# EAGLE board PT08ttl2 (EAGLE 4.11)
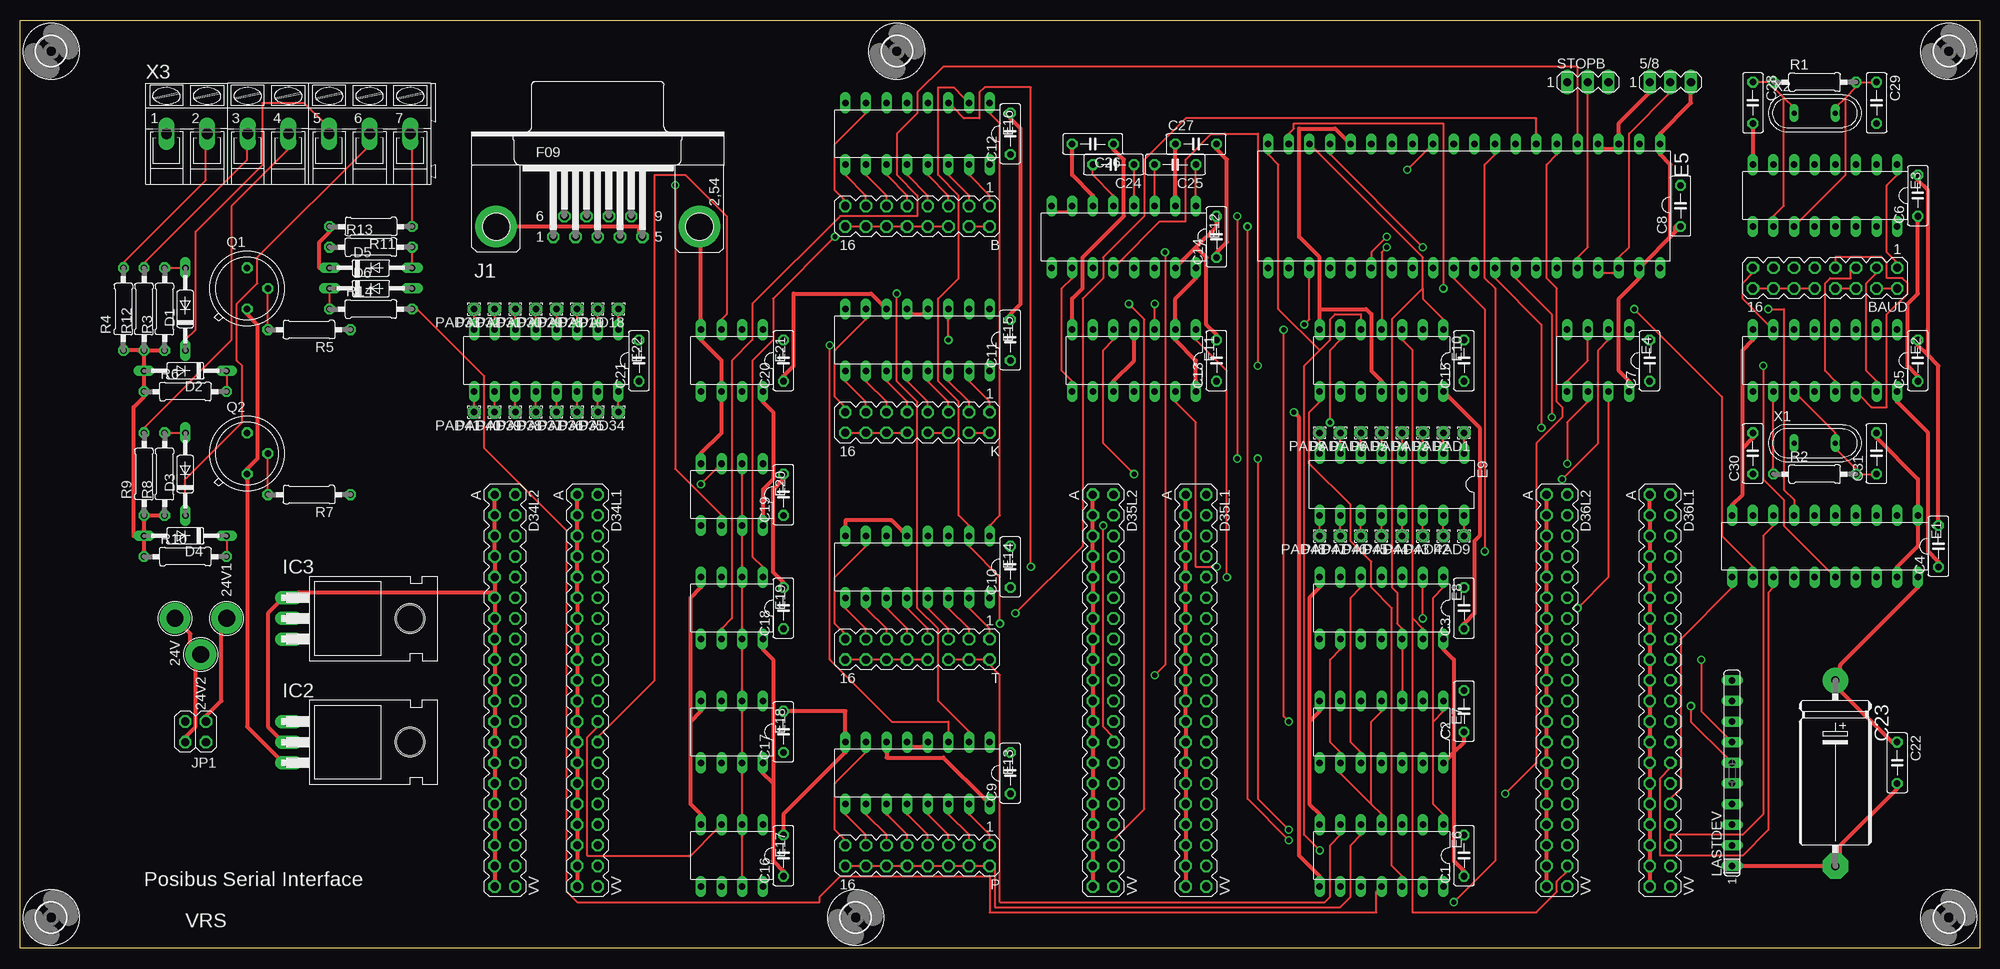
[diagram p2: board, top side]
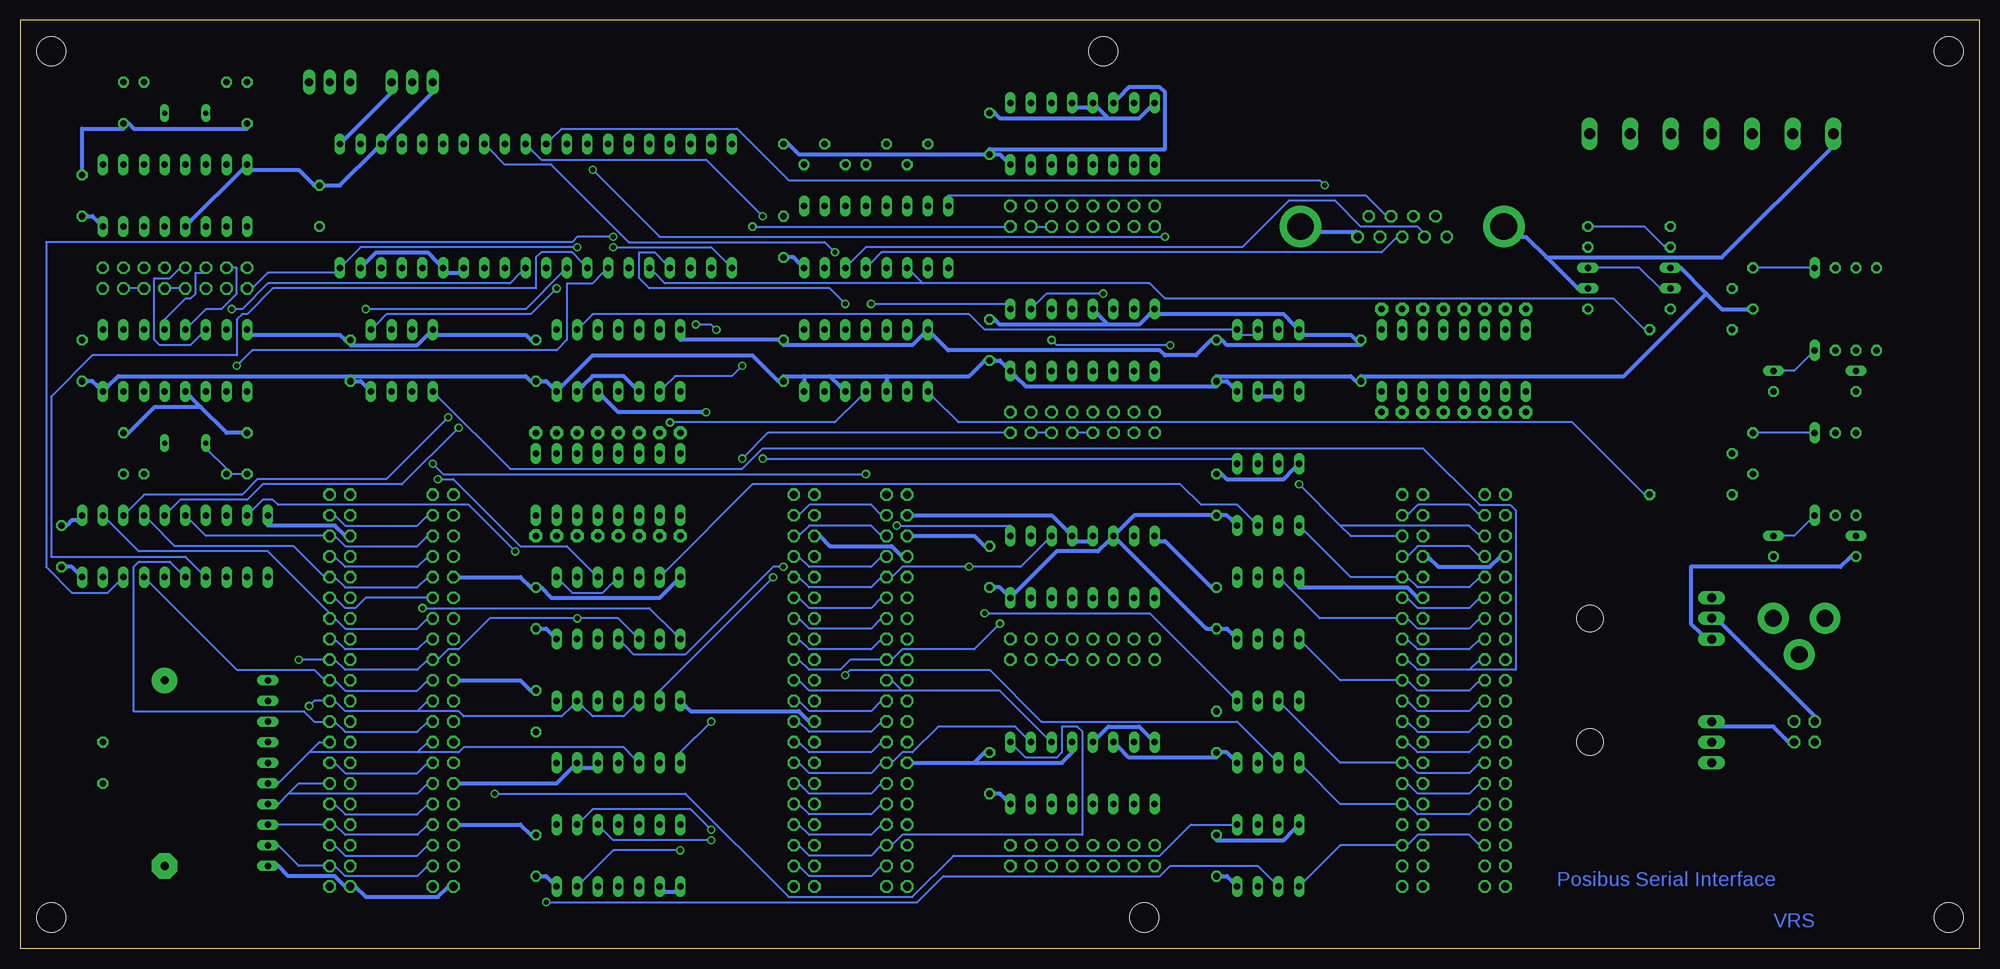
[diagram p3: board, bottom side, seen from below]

Size 241.3 x 114.3 mm. Coordinates in mm from the lower left corner, seen from the top.
Outline: 0,0 0,114.3 241.3,114.3 241.3,0 0,0
Copper layers (1*16): Top 0.035mm / dielectric 1.5mm / Bottom 0.035mm
Design rules "olimex10mil": minimum track width 10mil, minimum drill 24mil, track to track 10mil, track to pad 10mil, pad to pad 10mil, via to via 10mil, smd to smd 10mil, copper to edge 25mil, drill to drill 10mil, minimum pad ring 10mil, minimum via ring 8mil, stop-mask expansion 0mil, vias tented up to drill 0mil, thermal gap 10mil
Net classes: 1 supply: width 0.508 mm

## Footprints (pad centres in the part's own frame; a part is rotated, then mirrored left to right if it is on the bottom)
MA03-1 = drill 1.016 long: 1 -2.54,0; 2 0,0; 3 2.54,0
0820 = drill 2.083 pad 3.81 round: P$1 0,0
MA08-2 = drill 1.016 octagon: 1 -8.89,-1.27; 2 -8.89,1.27; 3 -6.35,-1.27; 4 -6.35,1.27; 5 -3.81,-1.27; 6 -3.81,1.27; 7 -1.27,-1.27; 8 -1.27,1.27; 9 1.27,-1.27; 10 1.27,1.27; 11 3.81,-1.27; 12 3.81,1.27; 13 6.35,-1.27; 14 6.35,1.27; 15 8.89,-1.27; 16 8.89,1.27
C050-025X075 = drill 0.813 octagon: 1 -2.54,0; 2 2.54,0
E22-9 = drill 1.016 pad 3.15 round: + -11.43,0 | drill 1.016 pad 3.15 octagon: - 11.43,0
DO35-10 = drill 0.813 long: A 5.08,0; C -5.08,0
DEC40PIN = drill 1.016 octagon: A -24.13,-1.27; AA 3.81,-1.27; B -24.13,1.27; BB 3.81,1.27; C -21.59,-1.27; CC 6.35,-1.27; D -21.59,1.27; DD 6.35,1.27; E -19.05,-1.27; EE 8.89,-1.27; F -19.05,1.27; FF 8.89,1.27; H -16.51,-1.27; HH 11.43,-1.27; J -16.51,1.27; JJ 11.43,1.27; K -13.97,-1.27; KK 13.97,-1.27; L -13.97,1.27; LL 13.97,1.27; M -11.43,-1.27; MM 16.51,-1.27; N -11.43,1.27; NN 16.51,1.27; P -8.89,-1.27; PP 19.05,-1.27; R -8.89,1.27; RR 19.05,1.27; S -6.35,-1.27; SS 21.59,-1.27; T -6.35,1.27; TT 21.59,1.27; U -3.81,-1.27; UU 24.13,-1.27; V -3.81,1.27; VV 24.13,1.27; W -1.27,-1.27; X -1.27,1.27; Y 1.27,-1.27; Z 1.27,1.27
DIL20 = drill 0.813 long: 1 -11.43,-3.81; 2 -8.89,-3.81; 3 -6.35,-3.81; 4 -3.81,-3.81; 5 -1.27,-3.81; 6 1.27,-3.81; 7 3.81,-3.81; 8 6.35,-3.81; 9 8.89,-3.81; 10 11.43,-3.81; 11 11.43,3.81; 12 8.89,3.81; 13 6.35,3.81; 14 3.81,3.81; 15 1.27,3.81; 16 -1.27,3.81; 17 -3.81,3.81; 18 -6.35,3.81; 19 -8.89,3.81; 20 -11.43,3.81
DIL16 = drill 0.813 long: 1 -8.89,-3.81; 2 -6.35,-3.81; 3 -3.81,-3.81; 4 -1.27,-3.81; 5 1.27,-3.81; 6 3.81,-3.81; 7 6.35,-3.81; 8 8.89,-3.81; 9 8.89,3.81; 10 6.35,3.81; 11 3.81,3.81; 12 1.27,3.81; 13 -1.27,3.81; 14 -3.81,3.81; 15 -6.35,3.81; 16 -8.89,3.81
DIL08 = drill 0.813 long: 1 -3.81,-3.81; 2 -1.27,-3.81; 3 1.27,-3.81; 4 3.81,-3.81; 5 3.81,3.81; 6 1.27,3.81; 7 -1.27,3.81; 8 -3.81,3.81
DIL40 = drill 0.813 long: 1 -24.13,-7.62; 2 -21.59,-7.62; 3 -19.05,-7.62; 4 -16.51,-7.62; 5 -13.97,-7.62; 6 -11.43,-7.62; 7 -8.89,-7.62; 8 -6.35,-7.62; 9 -3.81,-7.62; 10 -1.27,-7.62; 11 1.27,-7.62; 12 3.81,-7.62; 13 6.35,-7.62; 14 8.89,-7.62; 15 11.43,-7.62; 16 13.97,-7.62; 17 16.51,-7.62; 18 19.05,-7.62; 19 21.59,-7.62; 20 24.13,-7.62; 21 24.13,7.62; 22 21.59,7.62; 23 19.05,7.62; 24 16.51,7.62; 25 13.97,7.62; 26 11.43,7.62; 27 8.89,7.62; 28 6.35,7.62; 29 3.81,7.62; 30 1.27,7.62; 31 -1.27,7.62; 32 -3.81,7.62; 33 -6.35,7.62; 34 -8.89,7.62; 35 -11.43,7.62; 36 -13.97,7.62; 37 -16.51,7.62; 38 -19.05,7.62; 39 -21.59,7.62; 40 -24.13,7.62
DIL14 = drill 0.813 long: 1 -7.62,-3.81; 2 -5.08,-3.81; 3 -2.54,-3.81; 4 0,-3.81; 5 2.54,-3.81; 6 5.08,-3.81; 7 7.62,-3.81; 8 7.62,3.81; 9 5.08,3.81; 10 2.54,3.81; 11 0,3.81; 12 -2.54,3.81; 13 -5.08,3.81; 14 -7.62,3.81
TO220H = drill 1.118 long: 1 -2.54,-10.16; 2 0,-10.16; 3 2.54,-10.16 | hole 3.302: 0,4.826
F09HP = drill 1.016 octagon: 1 -5.486,-1.27; 2 -2.743,-1.27; 3 0,-1.27; 4 2.743,-1.27; 5 5.486,-1.27; 6 -4.115,1.27; 7 -1.372,1.27; 8 1.372,1.27; 9 4.115,1.27 | drill 3.302 pad 5.08 round: G1 -12.522,0; G2 12.522,0
2X02 = drill 1.016 octagon: 1 -1.27,-1.27; 2 -1.27,1.27; 3 1.27,-1.27; 4 1.27,1.27
SIL10 = drill 0.813 long: 1 -11.43,0; 2 -8.89,0; 3 -6.35,0; 4 -3.81,0; 5 -1.27,0; 6 1.27,0; 7 3.81,0; 8 6.35,0; 9 8.89,0; 10 11.43,0
1,6/0,8 = drill 0.813 pad 1.6 octagon: 1 0,0
TO39 = drill 0.813 octagon: 1 0,-2.54; 2 2.54,0; 3 0,2.54
0207/10 = drill 0.813 octagon: 1 -5.08,0; 2 5.08,0
3,6 = hole 3.6: 0,0
QS = drill 0.61 long: 1 -2.54,0; 2 2.54,0
AK300/7 = drill 1.321 long: 1 -15.011,0; 2 -10.008,0; 3 -5.004,0; 4 0,0; 5 5.004,0; 6 10.008,0; 7 15.011,0

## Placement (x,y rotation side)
5/8  [MA03-1]  203.2,106.68 0 top
24V  PAD-0820  [0820]  19.05,40.64 270 top
24V1  PAD-0820  [0820]  25.4,40.64 90 top
24V2  PAD-0820  [0820]  22.23,36.2 270 top
B  [MA08-2]  110.49,90.17 180 top
BAUD  [MA08-2]  222.25,82.55 180 top
C1  0.1  [C050-025X075]  177.8,11.43 90 top
C2  0.1  [C050-025X075]  177.8,29.21 90 top
C3  0.1  [C050-025X075]  177.8,41.91 90 top
C4  0.1  [C050-025X075]  236.22,49.53 90 top
C5  0.1  [C050-025X075]  233.68,72.39 90 top
C6  0.1  [C050-025X075]  233.68,92.71 90 top
C7  0.1  [C050-025X075]  200.66,72.39 90 top
C8  0.1  [C050-025X075]  204.47,91.44 90 top
C9  0.1  [C050-025X075]  121.92,21.59 90 top
C10  0.1  [C050-025X075]  121.92,46.99 90 top
C11  0.1  [C050-025X075]  121.92,74.93 90 top
C12  0.1  [C050-025X075]  121.92,100.33 90 top
C13  0.1  [C050-025X075]  147.32,72.39 90 top
C14  0.1  [C050-025X075]  147.32,87.63 90 top
C15  0.1  [C050-025X075]  177.8,72.39 90 top
C16  0.1  [C050-025X075]  93.98,11.43 90 top
C17  0.1  [C050-025X075]  93.98,26.67 90 top
C18  0.1  [C050-025X075]  93.98,41.91 90 top
C19  0.1  [C050-025X075]  93.98,55.88 90 top
C20  0.1  [C050-025X075]  93.98,72.39 90 top
C21  0.1  [C050-025X075]  76.2,72.39 90 top
C22  0.1  [C050-025X075]  231.14,22.86 270 top
C23  100uf  [E22-9]  223.52,21.59 270 top
C24  0.1  [C050-025X075]  134.62,96.52 180 top
C25  0.1  [C050-025X075]  142.24,96.52 180 top
C26  0.1  [C050-025X075]  132.08,99.06 180 top
C27  0.1  [C050-025X075]  144.78,99.06 0 top
C28  22pf  [C050-025X075]  213.36,104.14 270 top
C29  22pf  [C050-025X075]  228.6,104.14 270 top
C30  22pf  [C050-025X075]  213.36,60.96 90 top
C31  22pf  [C050-025X075]  228.6,60.96 90 top
D1  D664  [DO35-10]  20.32,78.74 90 top
D2  D664  [DO35-10]  20.32,71.12 180 top
D3  D664  [DO35-10]  20.32,58.42 90 top
D4  D664  [DO35-10]  20.32,50.8 180 top
D5  D664  [DO35-10]  43.18,83.82 0 top
D6  D664  [DO35-10]  43.18,81.28 0 top
D34L1  [DEC40PIN]  69.85,31.75 270 top
D34L2  [DEC40PIN]  59.69,31.75 270 top
D35L1  [DEC40PIN]  144.78,31.75 270 top
D35L2  [DEC40PIN]  133.35,31.75 270 top
D36L1  [DEC40PIN]  201.93,31.75 270 top
D36L2  [DEC40PIN]  189.23,31.75 270 top
E1  74HCT240N  [DIL20]  222.25,49.53 180 top
E2  74HCT4060N  [DIL16]  222.25,72.39 180 top
E3  74HCT4060N  [DIL16]  222.25,92.71 180 top
E4  DS75452N  [DIL08]  194.31,72.39 180 top
E5  HD6402  [DIL40]  177.8,91.44 180 top
E6  74LS02N  [DIL14]  167.64,11.43 180 top
E7  74HCT00N  [DIL14]  167.64,26.67 180 top
E8  74HCT08N  [DIL14]  167.64,41.91 180 top
E9  SPARE  [DIL16]  168.91,57.15 180 top
E10  74HCT04N  [DIL14]  167.64,72.39 180 top
E11  74HCT74N  [DIL14]  137.16,72.39 180 top
E12  MAX232  [DIL16]  135.89,87.63 180 top
E13  74LS138N  [DIL16]  110.49,21.59 180 top
E14  74LS138N  [DIL16]  110.49,46.99 180 top
E15  74LS138N  [DIL16]  110.49,74.93 180 top
E16  74LS138N  [DIL16]  110.49,100.33 180 top
E17  DS75452N  [DIL08]  87.63,11.43 180 top
E18  DS75452N  [DIL08]  87.63,26.67 180 top
E19  DS75452N  [DIL08]  87.63,41.91 180 top
E20  DS75452N  [DIL08]  87.63,55.88 180 top
E21  DS75452N  [DIL08]  87.63,72.39 180 top
E22  SPARE  [DIL16]  64.77,72.39 180 top
IC2  7805T  [TO220H]  43.18,25.4 270 top
IC3  7915T  [TO220H]  43.18,40.64 270 top
J1  [F09HP]  71.12,88.9 0 top
JP1  [2X02]  21.59,26.67 180 top
K  [MA08-2]  110.49,64.77 180 top
LASTDEV  100  [SIL10]  210.82,21.59 90 top
P  [MA08-2]  110.49,11.43 180 top
PAD1  [1,6/0,8]  177.8,63.5 180 top
PAD2  [1,6/0,8]  175.26,63.5 180 top
PAD3  [1,6/0,8]  172.72,63.5 180 top
PAD4  [1,6/0,8]  170.18,63.5 180 top
PAD5  [1,6/0,8]  167.64,63.5 180 top
PAD6  [1,6/0,8]  165.1,63.5 180 top
PAD7  [1,6/0,8]  162.56,63.5 180 top
PAD8  [1,6/0,8]  160.02,63.5 180 top
PAD9  [1,6/0,8]  177.8,50.8 180 top
PAD18  [1,6/0,8]  73.66,78.74 180 top
PAD19  [1,6/0,8]  71.12,78.74 180 top
PAD28  [1,6/0,8]  68.58,78.74 180 top
PAD29  [1,6/0,8]  66.04,78.74 180 top
PAD30  [1,6/0,8]  63.5,78.74 180 top
PAD31  [1,6/0,8]  60.96,78.74 180 top
PAD32  [1,6/0,8]  58.42,78.74 180 top
PAD33  [1,6/0,8]  55.88,78.74 180 top
PAD34  [1,6/0,8]  73.66,66.04 180 top
PAD35  [1,6/0,8]  71.12,66.04 180 top
PAD36  [1,6/0,8]  68.58,66.04 180 top
PAD37  [1,6/0,8]  66.04,66.04 180 top
PAD38  [1,6/0,8]  63.5,66.04 180 top
PAD39  [1,6/0,8]  60.96,66.04 180 top
PAD40  [1,6/0,8]  58.42,66.04 180 top
PAD41  [1,6/0,8]  55.88,66.04 180 top
PAD42  [1,6/0,8]  175.26,50.8 180 top
PAD43  [1,6/0,8]  172.72,50.8 180 top
PAD44  [1,6/0,8]  170.18,50.8 180 top
PAD45  [1,6/0,8]  167.64,50.8 180 top
PAD46  [1,6/0,8]  165.1,50.8 180 top
PAD47  [1,6/0,8]  162.56,50.8 180 top
PAD48  [1,6/0,8]  160.02,50.8 180 top
Q1  2N2904  [TO39]  27.94,81.28 0 top
Q2  2N2904  [TO39]  27.94,60.96 0 top
R1  10M  [0207/10]  220.98,106.68 0 top
R2  10M  [0207/10]  220.98,58.42 0 top
R3  1.5K 1/2W  [0207/10]  17.78,78.74 90 top
R4  750 1W  [0207/10]  12.7,78.74 90 top
R5  470  [0207/10]  35.56,76.2 180 top
R6  15K 1/2W  [0207/10]  20.32,68.58 0 top
R7  470  [0207/10]  35.56,55.88 180 top
R8  1.5K 1/2W  [0207/10]  17.78,58.42 90 top
R9  750 1W  [0207/10]  15.24,58.42 90 top
R10  15K 1/2W  [0207/10]  20.32,48.26 0 top
R11  750 1/2W  [0207/10]  43.18,88.9 180 top
R12  560 1/2W  [0207/10]  15.24,78.74 90 top
R13  82  [0207/10]  43.18,86.36 0 top
R14  3.3K  [0207/10]  43.18,78.74 0 top
STOPB  [MA03-1]  193.04,106.68 0 top
T  [MA08-2]  110.49,36.83 180 top
U$1  [3,6]  237.49,3.81 0 top
U$2  [3,6]  237.49,110.49 0 top
U$3  [3,6]  3.81,110.49 0 top
U$4  [3,6]  3.81,3.81 0 top
U$5  [3,6]  107.95,110.49 0 top
U$6  [3,6]  102.87,3.81 0 top
X1  2.4576Mhz  [QS]  220.98,62.23 0 top
X2  3.579545Mhz  [QS]  220.98,102.87 0 top
X3  [AK300/7]  33.02,100.33 0 top

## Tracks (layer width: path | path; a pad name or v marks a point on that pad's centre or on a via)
24V1
  Top 0.508: JP1.1 22.86,28.57 24.77,30.48 24.77,39.37 24V1.P$1
24V2
  Top 0.508: JP1.4 20.32,26.04 21.59,27.3 21.59,34.92 24V2.P$1 20.95,37.47 20.95,38.73 20.32,39.37 24V.P$1
+24V
  Bottom 0.508: JP1.2 23.5,25.4 25.4,27.3 31.75,27.3 IC2.1
-15V
  Top 0.508: R4.1 13.34,73.66 14.61,73.66 R12.1 | R3.1 17.14,73.66 15.88,73.66 R12.1 | R12.1 15.24,73.03 15.24,71.75 D2.A 15.24,70.48 15.24,69.22 R6.1 15.24,67.94 13.97,66.67 13.97,50.8 D4.A | R10.1 15.24,48.9 15.24,50.16 D4.A | D4.A 15.24,51.44 15.24,52.7 R9.1 15.88,53.34 17.14,53.34 R8.1
  Bottom 0.508: IC3.3 34.29,38.73 35.56,40.01 35.56,46.99 17.14,46.99 15.88,48.26 R10.1
-24V
  Bottom 0.508: JP1.3 20.32,28.57 31.75,40.01 IC3.2
ACB00\
  Bottom 0.254: D34L2.D 61.59,53.34 62.87,54.61 69.22,54.61 70.48,53.34 D34L1.D
ACB01\
  Bottom 0.254: D34L2.J 61.59,48.26 62.87,49.53 69.22,49.53 70.48,48.26 D34L1.J
ACB02\
  Bottom 0.254: D34L2.N 61.59,43.18 62.87,41.91 69.22,41.91 70.48,43.18 D34L1.N
ACB03\
  Bottom 0.254: D34L2.T 61.59,38.1 62.87,36.83 69.22,36.83 70.48,38.1 D34L1.T
ACB04\
  Bottom 0.254: E19.5 83.19,37.47 78.74,33.02 71.75,33.02 D34L1.X 70.48,33.02 69.22,31.75 62.87,31.75 61.59,33.02 D34L2.X
ACB05\
  Top 0.254: E17.3 85.72,14.61 82.55,11.43 69.85,11.43 69.85,26.04 71.12,27.3 D34L1.BB
  Bottom 0.254: D34L2.BB 61.59,27.94 62.87,26.67 69.22,26.67 70.48,27.94 D34L1.BB
ACB06\
  Bottom 0.254: E18.3 85.72,29.84 78.74,22.86 71.75,22.86 D34L1.FF 70.48,22.86 69.22,21.59 62.87,21.59 61.59,22.86 D34L2.FF
ACB07\
  Bottom 0.254: E18.5 83.19,22.23 78.74,17.78 71.75,17.78 D34L1.LL 70.48,17.78 69.22,16.51 62.87,16.51 61.59,17.78 D34L2.LL
ACB08\
  Bottom 0.254: E17.5 83.19,8.26 78.74,12.7 71.75,12.7 D34L1.RR 70.48,12.7 69.22,13.97 62.87,13.97 61.59,12.7 D34L2.RR
ACB09\  (via drill 0.61)
  Top 0.254: v83.82,57.15 85.72,59.05 E20.3
  Bottom 0.254: 78.74,52.07 77.47,50.8 71.75,50.8 D34L1.F | 78.74,52.07 v83.82,57.15 | 78.74,52.07 62.87,52.07 61.59,50.8 D34L2.F
ACB10\
  Bottom 0.254: E20.5 83.19,51.44 77.47,45.72 71.75,45.72 D34L1.L 70.48,45.72 69.22,44.45 62.87,44.45 61.59,45.72 D34L2.L
ACB11\
  Bottom 0.254: E19.3 85.72,45.09 81.28,40.64 71.75,40.64 D34L1.R 70.48,40.64 69.22,39.37 62.87,39.37 61.59,40.64 D34L2.R
ACCLEAR\
  Top 0.254: E21.3 86.36,77.47 87,78.11 87,90.17 81.92,95.25 78.11,95.25 78.11,33.02 71.12,26.04 D34L1.DD
  Bottom 0.254: D34L2.DD 61.59,25.4 62.87,24.13 69.22,24.13 70.48,25.4 D34L1.DD
B110
  Top 0.254: E3.1 231.14,95.25 229.87,93.98 229.87,85.72 231.14,84.45 BAUD.1
B150
  Top 0.254: E2.15 228.6,69.85 227.33,71.12 227.33,81.92 228.6,83.19 BAUD.3
B300
  Top 0.254: E2.13 223.52,69.85 222.25,71.12 222.25,81.92 222.88,82.55 225.43,82.55 225.43,83.82 BAUD.5
B600
  Top 0.254: E2.14 226.69,67.94 227.97,66.67 229.87,66.67 229.87,78.11 232.41,80.64 232.41,81.92 231.78,82.55 229.87,82.55 229.87,84.45 229.24,85.09 223.52,85.09 223.52,84.45 BAUD.7
B1200
  Bottom 0.254: E2.6 219.07,75.56 220.34,74.3 224.16,74.3 224.79,74.93 224.79,82.55 222.88,82.55 221.62,83.82 BAUD.9
B2400
  Bottom 0.254: E2.4 223.52,77.47 220.98,80.01 220.34,80.01 219.71,80.64 219.71,83.19 218.44,83.19 BAUD.11
B4800
  Bottom 0.254: E2.5 220.34,76.83 218.44,78.74 216.53,78.74 214.63,80.64 214.63,83.82 215.26,83.82 BAUD.13
B9600
  Top 0.254: E2.7 215.26,76.83 212.09,80.01 212.09,81.92 213.36,83.19 BAUD.15
B\  (via drill 0.61)
  Top 0.254: B.16 102.23,88.9 103.5,88.9 B.14 104.78,88.9 106.05,88.9 B.12 107.31,88.9 108.58,88.9 B.10 109.86,88.9 111.12,88.9 B.8 112.39,88.9 113.67,88.9 B.6 | v156.21,13.34 151.13,18.41 v151.13,88.9 | B.4 117.47,88.9 118.75,88.9 B.2
  Bottom 0.254: B.4 116.2,88.9 114.94,88.9 B.6 | v156.21,13.34 168.28,13.34 169.54,14.61 E6.3 | v151.13,88.9 120.02,88.9 B.2
BAC00
  Bottom 0.254: D36L2.D 191.13,53.34 192.41,52.07 201.29,52.07 202.56,53.34 D36L1.D
BAC01
  Bottom 0.254: D36L2.J 191.13,48.26 192.41,46.99 201.29,46.99 202.56,48.26 D36L1.J
BAC02
  Bottom 0.254: D36L2.N 191.13,43.18 198.75,43.18 200.03,41.91 201.29,41.91 202.56,43.18 D36L1.N
BAC03
  Bottom 0.254: D36L2.T 191.13,38.1 192.41,36.83 201.29,36.83 202.56,38.1 D36L1.T
BAC04
  Bottom 0.254: E1.17 225.43,45.09 214.63,34.29 205.1,34.29 203.84,33.02 D36L1.X 202.56,33.02 201.29,31.75 192.41,31.75 191.13,33.02 D36L2.X
BAC05
  Bottom 0.254: E1.15 221.62,46.35 222.88,47.62 226.69,47.62 227.33,46.99 227.33,29.21 206.38,29.21 205.1,27.94 203.84,27.94 D36L1.BB 202.56,27.94 201.29,26.67 192.41,26.67 191.13,27.94 D36L2.BB
BAC06
  Top 0.254: E1.13 215.9,44.45 215.26,43.81 215.26,14.61 212.09,11.43 201.93,11.43 201.93,20.95 203.2,22.23 D36L1.FF
  Bottom 0.254: D36L2.FF 191.13,22.86 192.41,21.59 201.29,21.59 202.56,22.86 D36L1.FF
BAC07
  Top 0.254: E1.11 210.82,44.45 204.47,38.1 204.47,19.68 203.2,18.41 D36L1.LL
  Bottom 0.254: D36L2.LL 191.13,17.78 192.41,16.51 201.29,16.51 202.56,17.78 D36L1.LL
BAC08
  Top 0.254: E1.8 215.9,52.07 214.63,50.8 214.63,16.51 212.09,13.97 203.2,13.97 203.2,13.34 D36L1.RR
  Bottom 0.254: D36L2.RR 191.13,12.7 192.41,11.43 201.29,11.43 202.56,12.7 D36L1.RR
BAC09
  Bottom 0.254: E1.6 220.34,52.7 218.44,50.8 203.84,50.8 D36L1.F 202.56,50.8 201.29,49.53 192.41,49.53 191.13,50.8 D36L2.F
BAC10
  Bottom 0.254: E1.4 225.43,52.7 222.25,49.53 207.65,49.53 203.84,45.72 D36L1.L 202.56,45.72 201.29,44.45 192.41,44.45 191.13,45.72 D36L2.L
BAC11
  Bottom 0.254: E1.2 230.5,52.7 226.69,48.9 210.82,48.9 203.2,41.27 D36L1.R 202.56,40.64 201.29,39.37 192.41,39.37 191.13,40.64 D36L2.R
BCLK  (via drill 0.61)
  Top 0.254: BAUD.16 214,81.28 215.26,81.28 BAUD.14 216.53,81.28 217.81,81.28 BAUD.12 219.07,81.28 220.34,81.28 BAUD.10 | BAUD.6 225.43,81.28 224.16,81.28 BAUD.8 | BAUD.2 230.5,81.28 229.24,81.28 BAUD.4 | v172.72,86.36 161.29,97.79 E5.17
  Bottom 0.254: BAUD.8 222.88,81.28 221.62,81.28 BAUD.10 | BAUD.4 227.97,81.28 226.69,81.28 BAUD.6 | v172.72,86.36 199.39,86.36 201.29,84.45 E5.40 202.56,83.19 210.82,83.19 212.72,81.28 BAUD.16
BINIT\
  Top 0.254: 171.45,40.64 172.72,39.37 E8.13 | 171.45,40.64 171.45,73.66 170.18,74.93 E10.3 | 171.45,40.64 171.45,4.45 186.69,4.45 189.23,6.99 189.23,8.26 190.5,9.53 D36L2.TT
  Bottom 0.254: LASTDEV.2 209.55,12.7 207.01,10.16 203.84,10.16 D36L1.TT 202.56,10.16 201.29,8.89 192.41,8.89 191.13,10.16 D36L2.TT
BIOP1  (via drill 0.61)
  Top 0.254: v207.01,35.56 207.01,29.21 210.19,26.04 LASTDEV.7 | v172.72,40.64 172.72,44.45 E8.2
  Bottom 0.254: v207.01,35.56 203.84,35.56 D36L1.V 202.56,35.56 201.29,34.29 192.41,34.29 191.13,35.56 D36L2.V 189.87,35.56 188.59,36.83 187.32,36.83 183.51,40.64 v172.72,40.64 167.64,40.64 165.74,38.73 E8.10
BIOP2  (via drill 0.61)
  Top 0.254: v205.74,29.84 205.74,27.94 210.19,23.5 LASTDEV.6
  Bottom 0.254: E7.5 165.74,29.84 167,28.57 170.81,28.57 172.09,29.84 E7.2 173.35,29.84 174.62,28.57 186.69,28.57 187.32,29.21 192.41,29.21 | v205.74,29.84 205.1,30.48 203.84,30.48 D36L1.Z 202.56,30.48 201.29,29.21 192.41,29.21 | 192.41,29.21 191.13,30.48 D36L2.Z
BIOP4
  Top 0.254: E7.10 165.1,24.13 163.83,25.4 163.83,43.18 165.1,44.45 E8.5
  Bottom 0.254: 205.74,24.13 204.47,25.4 203.84,25.4 D36L1.DD | 205.74,24.13 209.55,20.32 LASTDEV.5 | 192.41,24.13 191.13,25.4 D36L2.DD | 192.41,24.13 205.74,24.13 | 192.41,24.13 187.32,24.13 186.69,24.77 167,24.77 165.74,23.5 E7.10
BMB00
  Bottom 0.254: D35L2.D 135.25,53.34 136.53,54.61 144.15,54.61 145.41,53.34 D35L1.D
BMB01
  Bottom 0.254: D35L2.J 135.25,48.26 136.53,46.99 144.15,46.99 145.41,48.26 D35L1.J
BMB02
  Bottom 0.254: D35L2.N 135.25,43.18 136.53,41.91 144.15,41.91 145.41,43.18 D35L1.N
BMB03  (via drill 0.61)
  Top 0.254: v114.3,74.93 114.3,77.47 E15.3 | v99.69,74.3 99.69,35.56 107.31,27.94 114.3,27.94 114.3,26.67 E13.3
  Bottom 0.254: 132.72,31.75 120.65,31.75 114.94,26.04 E13.3 | 132.72,31.75 133.99,33.02 D35L2.X | v114.3,74.93 113.67,74.3 v99.69,74.3 | 132.72,31.75 144.15,31.75 145.41,33.02 D35L1.X
BMB03\
  Bottom 0.254: D35L2.T 135.25,38.1 136.53,36.83 144.15,36.83 145.41,38.1 D35L1.T
BMB04  (via drill 0.61)
  Top 0.254: v107.95,80.64 107.95,69.85 110.49,67.31 110.49,41.91 113.03,39.37 113.03,30.48 116.84,26.67 E13.2
  Bottom 0.254: E13.2 117.47,26.04 118.75,27.3 128.27,27.3 131.44,24.13 132.72,24.13 133.99,22.86 D35L2.FF 135.25,22.86 136.53,21.59 144.15,21.59 145.41,22.86 D35L1.FF | v107.95,80.64 114.94,80.64 116.2,79.38 E15.2
BMB04\
  Bottom 0.254: D35L2.BB 135.25,27.94 136.53,26.67 144.15,26.67 145.41,27.94 D35L1.BB
BMB05  (via drill 0.61)
  Top 0.254: v136.53,79.38 138.43,77.47 138.43,17.14 134.62,13.34 D35L2.RR
  Bottom 0.254: E13.1 118.75,24.77 117.47,23.5 113.67,23.5 113.03,24.13 113.03,27.3 111.12,27.3 110.49,26.67 110.49,13.97 132.72,13.97 133.99,12.7 D35L2.RR 135.25,12.7 136.53,11.43 144.15,11.43 145.41,12.7 D35L1.RR | v136.53,79.38 120.02,79.38 E15.1
BMB05\
  Bottom 0.254: D35L2.LL 135.25,17.78 136.53,16.51 144.15,16.51 145.41,17.78 D35L1.LL
BMB06  (via drill 0.61)
  Top 0.254: v124.46,46.99 124.46,106.05 118.75,106.05 118.11,105.41 118.11,102.23 116.2,102.23 114.94,103.5 E16.3
  Bottom 0.254: E14.3 114.94,50.16 118.11,46.99 v124.46,46.99 132.72,46.99 133.99,45.72 D35L2.L 135.25,45.72 136.53,44.45 144.15,44.45 145.41,45.72 D35L1.L
BMB06\
  Bottom 0.254: D35L2.F 135.25,50.8 136.53,52.07 144.15,52.07 145.41,50.8 D35L1.F
BMB07  (via drill 0.61)
  Top 0.254: v120.65,40.01 120.65,45.72 116.84,49.53 E14.2 116.84,52.07 115.57,53.34 115.57,67.31 113.03,69.85 113.03,80.01 115.57,82.55 115.57,92.71 113.03,95.25 113.03,106.05 114.94,106.05 116.2,104.78 E16.2
  Bottom 0.254: v120.65,40.01 123.83,36.83 132.72,36.83 133.99,35.56 D35L2.V 135.25,35.56 139.06,35.56 140.34,34.29 144.15,34.29 145.41,35.56 D35L1.V
BMB07\
  Bottom 0.254: D35L2.R 135.25,40.64 136.53,39.37 144.15,39.37 145.41,40.64 D35L1.R
BMB08  (via drill 0.61)
  Top 0.254: E14.1 119.38,52.07 120.65,53.34 120.65,101.6 119.38,102.87 E16.1 | v133.35,52.07 133.35,27.3 134.62,26.04 D35L2.DD
  Bottom 0.254: D35L2.DD 135.25,25.4 136.53,24.13 144.15,24.13 145.41,25.4 D35L1.DD | v133.35,52.07 119.38,52.07 E14.1
BMB08\
  Bottom 0.254: D35L2.Z 135.25,30.48 136.53,29.21 144.15,29.21 145.41,30.48 D35L1.Z
BMB09
  Bottom 0.254: D35L2.JJ 135.25,20.32 136.53,19.05 144.15,19.05 145.41,20.32 D35L1.JJ
BMB10
  Bottom 0.254: D35L2.NN 135.25,15.24 136.53,13.97 144.15,13.97 145.41,15.24 D35L1.NN
BMB11
  Bottom 0.254: D35L2.TT 135.25,10.16 136.53,8.89 144.15,8.89 145.41,10.16 D35L1.TT
BRUN\
  Bottom 0.254: D34L2.JJ 61.59,20.32 62.87,19.05 69.22,19.05 70.48,20.32 D34L1.JJ
BTS1
  Bottom 0.254: LASTDEV.3 209.55,15.24 203.84,15.24 D36L1.NN 202.56,15.24 201.29,13.97 192.41,13.97 191.13,15.24 D36L2.NN
BTS3
  Bottom 0.254: 208.28,19.05 207.01,20.32 203.84,20.32 D36L1.JJ | 208.28,19.05 209.55,17.78 LASTDEV.4 | 208.28,19.05 192.41,19.05 191.13,20.32 D36L2.JJ
CS8
  Top 0.254: E5.37 194.94,83.19 196.22,83.19 E5.38 196.85,85.09 198.12,86.36 198.12,100.33 203.2,105.41 5/8.2
GND
  Top 0.508: 144.78,86.36 147.32,88.9 147.32,89.53 C14.2 | 144.78,86.36 142.88,84.45 E12.15 | C26.1 134.62,98.42 135.89,97.16 135.89,90.17 130.81,85.09 130.81,81.28 129.54,80.01 129.54,77.47 E11.7 | 160.02,78.74 165.74,78.74 166.37,78.11 166.37,71.12 167.64,69.85 E10.11 | 160.02,78.74 160.02,77.47 E10.7 | 160.02,78.74 160.02,85.09 157.48,87.63 157.48,100.97 161.93,100.97 163.19,99.69 E5.16 | 144.78,86.36 146.05,85.09 146.05,76.83 147.32,75.56 C13.2 | E15.4 111.12,78.11 109.86,78.11 E15.5 | E20.4 83.82,60.96 86.36,63.5 86.36,67.31 E21.6 86.36,69.85 86.36,72.39 83.82,74.93 E21.4 83.82,77.47 83.82,87 J1.G2 | C12.2 121.92,102.23 123.19,100.97 123.19,79.38 121.92,78.11 C11.2 | J1.G1 60.96,88.9 76.2,88.9 76.2,88.27 J1.5 | D36L2.A 187.96,55.24 187.96,53.98 D36L2.C 187.96,52.7 187.96,51.44 D36L2.E 187.96,50.16 187.96,48.9 D36L2.H 187.96,47.62 187.96,46.35 D36L2.K 187.96,45.09 187.96,43.81 D36L2.M 187.96,42.55 187.96,41.27 D36L2.P 187.96,40.01 187.96,38.73 D36L2.S 187.96,37.47 187.96,36.2 D36L2.U 187.96,34.92 187.96,33.66 D36L2.W 187.96,32.38 187.96,31.11 D36L2.Y 187.96,29.84 187.96,28.57 D36L2.AA 187.96,27.3 187.96,26.04 D36L2.CC 187.96,24.77 187.96,23.5 D36L2.EE 187.96,22.23 187.96,20.95 D36L2.HH 187.96,19.68 187.96,18.41 D36L2.KK 187.96,17.14 187.96,15.88 D36L2.MM 187.96,14.61 187.96,13.34 D36L2.PP 187.96,12.06 187.96,10.79 D36L2.SS 187.96,9.53 187.96,8.26 D36L2.UU | LASTDEV.1 212.09,10.16 222.25,10.16 C23.- 224.16,11.43 224.16,12.7 231.14,19.68 C22.2 | D36L1.UU 200.66,8.26 200.66,9.53 D36L1.SS 200.66,10.79 200.66,12.06 D36L1.PP 200.66,13.34 200.66,14.61 D36L1.MM 200.66,15.88 200.66,17.14 D36L1.KK 200.66,18.41 200.66,19.68 D36L1.HH 200.66,20.95 200.66,22.23 D36L1.EE 200.66,23.5 200.66,24.77 D36L1.CC 200.66,26.04 200.66,27.3 D36L1.AA 200.66,28.57 200.66,29.84 D36L1.Y 200.66,31.11 200.66,32.38 D36L1.W 200.66,33.66 200.66,34.92 D36L1.U 200.66,36.2 200.66,37.47 D36L1.S 200.66,38.73 200.66,40.01 D36L1.P 200.66,41.27 200.66,42.55 D36L1.M 200.66,43.81 200.66,45.09 D36L1.K 200.66,46.35 200.66,47.62 D36L1.H 200.66,48.9 200.66,50.16 D36L1.E 200.66,51.44 200.66,52.7 D36L1.C 200.66,53.98 200.66,55.24 D36L1.A
  Top 0.508: E5.4 194.94,98.42 196.22,98.42 E5.3 196.85,100.33 196.85,101.6 200.66,105.41 5/8.1 | C28.2 213.36,100.97 213.36,97.79 E3.8 | 212.09,61.59 212.09,55.88 210.82,54.61 E1.10 | 212.09,61.59 213.36,62.87 C30.2 | E1.19 231.14,46.99 233.68,49.53 233.68,52.07 E1.1 233.68,54.61 233.68,57.78 228.6,62.87 C31.2 | 234.95,73.03 236.22,71.75 236.22,52.7 C4.2 | 234.95,73.03 233.68,74.3 C5.2 | 212.09,61.59 212.09,73.66 213.36,74.93 E2.8 | 234.95,73.03 234.95,93.34 233.68,94.61 C6.2 | 158.75,27.94 158.75,17.78 160.02,16.51 E6.7 | 158.75,27.94 160.02,29.21 E7.7 | 158.75,27.94 158.75,43.18 160.02,44.45 E8.7 | D35L1.UU 143.51,8.26 143.51,9.53 D35L1.SS 143.51,10.79 143.51,12.06 D35L1.PP 143.51,13.34 143.51,14.61 D35L1.MM 143.51,15.88 143.51,17.14 D35L1.KK 143.51,18.41 143.51,19.68 D35L1.HH 143.51,20.95 143.51,22.23 D35L1.EE 143.51,23.5 143.51,24.77 D35L1.CC 143.51,26.04 143.51,27.3 D35L1.AA 143.51,28.57 143.51,29.84 D35L1.Y 143.51,31.11 143.51,32.38 D35L1.W 143.51,33.66 143.51,34.92 D35L1.U 143.51,36.2 143.51,37.47 D35L1.S 143.51,38.73 143.51,40.01 D35L1.P 143.51,41.27 143.51,42.55 D35L1.M 143.51,43.81 143.51,45.09 D35L1.K 143.51,46.35 143.51,47.62 D35L1.H 143.51,48.9 143.51,50.16 D35L1.E 143.51,51.44 143.51,52.7 D35L1.C 143.51,53.98 143.51,55.24 D35L1.A | E14.5 108.58,51.44 107.31,52.7 101.6,52.7 101.6,52.07 E14.8 | D35L2.A 132.08,55.24 132.08,53.98 D35L2.C 132.08,52.7 132.08,51.44 D35L2.E 132.08,50.16 132.08,48.9 D35L2.H 132.08,47.62 132.08,46.35 D35L2.K 132.08,45.09 132.08,43.81 D35L2.M 132.08,42.55 132.08,41.27 D35L2.P 132.08,40.01 132.08,38.73 D35L2.S 132.08,37.47 132.08,36.2 D35L2.U 132.08,34.92 132.08,33.66 D35L2.W 132.08,32.38 132.08,31.11 D35L2.Y 132.08,29.84 132.08,28.57 D35L2.AA 132.08,27.3 132.08,26.04 D35L2.CC 132.08,24.77 132.08,23.5 D35L2.EE 132.08,22.23 132.08,20.95 D35L2.HH 132.08,19.68 132.08,18.41 D35L2.KK 132.08,17.14 132.08,15.88 D35L2.MM 132.08,14.61 132.08,13.34 D35L2.PP 132.08,12.06 132.08,10.79 D35L2.SS 132.08,9.53 132.08,8.26 D35L2.UU
  Top 0.508: E13.5 109.86,24.77 111.12,24.77 E13.4 | IC2.2 31.75,26.04 30.48,27.3 30.48,41.27 31.75,42.55 IC3.1 34.29,43.81 58.42,43.81 | D34L2.UU 58.42,8.26 58.42,9.53 D34L2.SS 58.42,10.79 58.42,12.06 D34L2.PP 58.42,13.34 58.42,14.61 D34L2.MM 58.42,15.88 58.42,17.14 D34L2.KK 58.42,18.41 58.42,19.68 D34L2.HH 58.42,20.95 58.42,22.23 D34L2.EE 58.42,23.5 58.42,24.77 D34L2.CC 58.42,26.04 58.42,27.3 D34L2.AA 58.42,28.57 58.42,29.84 D34L2.Y 58.42,31.11 58.42,32.38 D34L2.W 58.42,33.66 58.42,34.92 D34L2.U 58.42,36.2 58.42,37.47 D34L2.S 58.42,38.73 58.42,40.01 D34L2.P 58.42,41.27 58.42,42.55 D34L2.M | 58.42,43.81 58.42,45.09 D34L2.K 58.42,46.35 58.42,47.62 D34L2.H 58.42,48.9 58.42,50.16 D34L2.E 58.42,51.44 58.42,52.7 D34L2.C 58.42,53.98 58.42,55.24 D34L2.A | 58.42,43.81 D34L2.M | 58.42,43.81 D34L2.M | D34L1.UU 68.58,8.26 68.58,9.53 D34L1.SS 68.58,10.79 68.58,12.06 D34L1.PP 68.58,13.34 68.58,14.61 D34L1.MM 68.58,15.88 68.58,17.14 D34L1.KK 68.58,18.41 68.58,19.68 D34L1.HH 68.58,20.95 68.58,22.23 D34L1.EE 68.58,23.5 68.58,24.77 D34L1.CC 68.58,26.04 68.58,27.3 D34L1.AA 68.58,28.57 68.58,29.84 D34L1.Y 68.58,31.11 68.58,32.38 D34L1.W 68.58,33.66 68.58,34.92 D34L1.U 68.58,36.2 68.58,37.47 D34L1.S 68.58,38.73 68.58,40.01 D34L1.P 68.58,41.27 68.58,42.55 D34L1.M 68.58,43.81 68.58,45.09 D34L1.K 68.58,46.35 68.58,47.62 D34L1.H 68.58,48.9 68.58,50.16 D34L1.E 68.58,51.44 68.58,52.7 D34L1.C 68.58,53.98 68.58,55.24 D34L1.A | C17.2 94.61,29.21 101.6,29.21 101.6,26.67 E13.8 101.6,24.13 93.98,16.51 93.98,14.61 C16.2 | 82.55,27.94 83.82,29.21 E18.4
  Top 0.508: 82.55,27.94 82.55,17.78 83.82,16.51 E17.4 | 82.55,27.94 82.55,43.18 83.82,44.45 E19.4 | C19.2 93.98,57.78 92.71,56.52 92.71,46.35 93.98,45.09 C18.2
  Bottom 0.508: E10.7 160.02,74.93 147.96,74.93 C13.2 147.32,74.3 131.44,74.3 130.18,75.56 E11.7 128.91,75.56 127,73.66 100.97,73.66 100.33,73.03 96.52,73.03 94.61,74.93 C20.2 93.34,74.93 92.71,74.3 76.2,74.3 C21.2 76.83,74.93 77.47,75.56 83.19,75.56 E21.4 84.45,76.83 85.72,78.11 100.97,78.11 E15.8 102.23,78.11 103.5,76.83 107.31,76.83 | 53.34,85.09 55.88,87.63 56.52,87.63 J1.G1 | 53.34,85.09 49.53,81.28 D6.A | 53.34,85.09 31.75,85.09 18.41,98.42 X3.1 | J1.5 76.83,88.27 81.28,88.27 J1.G2 | 107.31,102.23 103.5,102.23 102.23,103.5 E16.8 | 107.31,102.23 108.58,103.5 E16.5 109.86,103.5 111.12,103.5 E16.4 | 107.31,102.23 120.65,102.23 121.28,102.87 C12.2 | 107.31,76.83 108.58,78.11 E15.5 | 107.31,76.83 120.65,76.83 121.28,77.47 C11.2 | E21.7 88.27,67.94 87,67.94 E21.6 | C19.2 93.34,58.42 92.71,57.78 85.72,57.78 84.45,59.05 E20.4 | C2.2 178.44,31.75 179.71,33.02 187.32,33.02 D36L2.W | D36L2.K 187.32,45.72 179.71,45.72 178.44,44.45 C3.2 177.16,44.45 175.9,43.18 162.56,43.18 160.66,45.09 E8.7 | E7.12 170.81,22.23 172.09,22.23 E7.13 173.35,22.23 175.26,20.32 187.32,20.32 D36L2.HH | C1.2 178.44,13.97 179.71,15.24 187.32,15.24 D36L2.MM | LASTDEV.1 209.55,10.16 208.28,8.89 202.56,8.89 201.29,7.62 D36L1.UU 200.03,7.62 198.75,6.35 189.87,6.35 188.59,7.62 D36L2.UU | STOPB.1 190.5,105.41 196.22,99.69 E5.3 197.49,98.42 201.93,93.98 203.84,93.98 C8.2 205.1,93.98 207.01,95.89 212.72,95.89 E3.8 214,95.89 220.34,89.53 E3.12 | C6.2 233.68,95.89 233.68,100.97 228.6,100.97 C29.2 227.97,101.6 227.33,100.97 213.36,100.97 C28.2 | C15.2 178.44,74.93 179.07,75.56 189.87,75.56 E4.4 191.13,75.56 192.41,74.3 200.66,74.3 C7.2 201.29,74.93 201.93,75.56 212.72,75.56 E2.8
  Bottom 0.508: 219.07,66.67 215.9,63.5 214,63.5 C30.2 | 219.07,66.67 220.34,67.94 E2.12 | 219.07,66.67 224.79,66.67 227.97,63.5 C31.2 | C4.2 235.59,52.07 234.95,52.7 234.31,52.7 E1.1 | D36L1.E 201.29,50.8 202.56,52.07 210.82,52.07 E1.10 | E7.7 159.38,29.84 158.75,29.21 145.41,29.21 144.15,27.94 D35L1.AA | E14.5 109.86,50.16 111.12,50.16 E14.4 112.39,51.44 114.3,53.34 131.44,53.34 D35L2.C | C18.2 94.61,44.45 100.33,50.16 100.97,50.16 E14.8 | C10.2 122.56,49.53 123.83,50.8 131.44,50.8 D35L2.E | 123.83,22.86 122.56,24.13 C9.2 | 123.83,22.86 131.44,22.86 D35L2.EE | 123.83,22.86 113.03,22.86 111.76,24.13 E13.4 | D35L1.E 142.88,50.8 141.6,49.53 133.99,49.53 132.72,48.26 D35L2.H | E17.4 84.45,14.61 85.72,13.34 93.98,13.34 C16.2 | D34L1.M 69.22,43.18 70.48,44.45 83.82,44.45 E19.4 | D34L2.H 59.05,48.26 60.33,46.99 66.67,46.99 67.94,48.26 D34L1.H | E13.5 108.58,26.04 107.31,27.3 103.5,27.3 102.23,26.04 E13.8
INT_RQ\
  Bottom 0.254: D34L2.Z 61.59,30.48 62.87,29.21 69.22,29.21 70.48,30.48 D34L1.Z
IOS\
  Top 0.254: E4.5 190.5,69.85 193.04,72.39 193.04,74.93 E4.3
  Bottom 0.254: 62.87,34.29 61.59,35.56 D34L2.V | 62.87,34.29 69.22,34.29 70.48,35.56 D34L1.V | 62.87,34.29 57.15,34.29 57.15,53.98 57.78,54.61 61.59,54.61 68.58,61.59 149.86,61.59 152.4,59.05 180.97,59.05 189.87,67.94 E4.5
K\  (via drill 0.61)
  Top 0.254: K.16 102.23,63.5 103.5,63.5 K.14 104.78,63.5 106.05,63.5 K.12 107.31,63.5 108.58,63.5 K.10 | K.6 113.67,63.5 112.39,63.5 K.8 | v156.21,14.61 152.4,18.41 v152.4,60.33 | K.4 117.47,63.5 118.75,63.5 K.2
  Bottom 0.254: K.8 111.12,63.5 109.86,63.5 K.10 | K.4 116.2,63.5 114.94,63.5 K.6 | v156.21,14.61 158.75,17.14 170.81,17.14 172.09,15.88 E6.2 | v152.4,60.33 149.22,63.5 120.02,63.5 K.2
KB
  Top 0.254: 173.99,27.94 173.99,17.78 175.26,16.51 E6.1 | 173.99,27.94 175.26,29.21 E7.1 | 173.99,27.94 173.99,43.18 175.26,44.45 E8.1
  Bottom 0.254: E8.4 168.28,45.09 169.54,43.81 173.35,43.81 174.62,45.09 E8.1
KBF  (via drill 0.61)
  Top 0.254: v175.26,81.28 175.26,101.6 156.84,101.6 156.84,100.97 156.21,100.33 E5.19
  Bottom 0.254: v175.26,81.28 178.44,78.11 196.22,78.11 197.49,76.83 E4.1
KCC
  Bottom 0.254: E21.2 89.53,75.56 90.81,75.56 E21.1 92.08,76.2 122.56,76.2 124.46,78.11 170.81,78.11 172.09,76.83 E10.2
KCC\
  Top 0.254: E7.3 170.18,31.75 170.18,36.83 E8.12 170.18,39.37 169.54,40.01 169.54,43.81 168.91,44.45 168.91,77.47 172.72,81.28 | 172.72,81.28 172.72,80.01 175.26,77.47 E10.1 | 172.72,81.28 172.72,85.09 159.38,98.42 E5.18
KRS
  Top 0.254: E17.7 88.9,8.89 88.9,13.97 E17.2 88.9,16.51 88.9,21.59 E18.7 88.9,24.13 88.9,29.21 E18.2 88.9,31.75 88.9,36.83 E19.7 88.9,39.37 88.9,44.45 E19.2 88.9,46.99 88.9,50.8 E20.7 88.9,53.34 88.9,58.42 E20.2
  Bottom 0.254: E8.6 161.93,46.35 151.13,57.15 98.42,57.15 95.89,54.61 91.44,54.61 89.53,52.7 E20.7
KSF  (via drill 0.61)
  Top 0.254: v189.87,57.78 194.31,62.23 194.31,73.66 195.58,74.93 E4.2
  Bottom 0.254: v189.87,57.78 187.96,57.78 179.71,49.53 173.99,49.53 170.81,46.35 E8.3
MR  (via drill 0.61)
  Top 0.254: v168.28,86.36 167.64,85.72 167.64,77.47 E10.4
  Bottom 0.254: v168.28,86.36 156.21,86.36 154.31,84.45 E5.21
N$1
  Top 0.254: E16.9 101.6,95.25 104.14,92.71 104.14,92.08 B.13
N$2
  Top 0.254: E9.1 177.8,62.23 177.8,62.87 PAD1.1
N$3
  Top 0.254: E9.2 175.26,62.23 175.26,62.87 PAD2.1
N$4
  Top 0.254: E9.3 172.72,62.23 172.72,62.87 PAD3.1
N$5
  Top 0.254: E16.15 116.84,95.25 119.38,92.71 119.38,92.08 B.1
N$6
  Top 0.254: E16.14 114.3,95.25 116.84,92.71 116.84,92.08 B.3
N$7
  Top 0.254: E16.13 111.76,95.25 114.3,92.71 114.3,92.08 B.5
N$8
  Top 0.254: E16.12 109.22,95.25 111.76,92.71 111.76,92.08 B.7
N$9
  Top 0.254: E16.11 106.68,95.25 109.22,92.71 109.22,92.08 B.9
N$10
  Top 0.254: E16.10 104.14,95.25 106.68,92.71 106.68,92.08 B.11
N$11
  Top 0.254: E16.7 104.14,102.87 100.33,99.06 100.33,93.34 101.6,92.08 B.15
N$12
  Top 0.254: E9.4 170.18,62.23 170.18,62.87 PAD4.1
N$13
  Top 0.254: 224.79,104.78 226.06,106.05 R1.2 226.69,106.68 227.97,106.68 C29.1 | 224.79,104.78 223.52,103.5 X2.2 | 224.79,104.78 224.79,95.25 219.07,89.53 E3.11
N$14
  Top 0.254: 217.17,104.78 215.9,106.05 R1.1 215.26,106.68 214,106.68 C28.1 | 217.17,104.78 218.44,103.5 X2.1 | 217.17,104.78 217.17,91.44 215.9,90.17 E3.10
N$15
  Top 0.508: E12.6 132.08,92.71 129.54,95.25 129.54,98.42 C26.2
N$16
  Top 0.508: E12.2 142.24,92.71 142.24,98.42 C27.1
N$17
  Top 0.254: R5.2 30.48,76.83 30.48,80.64 Q1.2
N$18
  Top 0.254: R3.2 18.41,83.82 19.68,83.82 D1.A
  Bottom 0.254: Q1.3 27.3,83.82 20.95,83.82 D1.A
N$19
  Top 0.254: R7.2 30.48,56.52 30.48,60.33 Q2.2
N$20
  Top 0.254: R8.2 18.41,63.5 19.68,63.5 D3.A
  Bottom 0.254: Q2.3 27.3,63.5 20.95,63.5 D3.A
N$21
  Top 0.254: E9.5 167.64,62.23 167.64,62.87 PAD5.1
N$22
  Top 0.254: E12.5 134.62,92.71 132.08,95.25 132.08,95.89 C24.2
N$23
  Top 0.254: E2.10 215.9,67.31 215.9,59.05 R2.1
  Bottom 0.254: X1.1 218.44,61.59 215.9,59.05 R2.1 215.26,58.42 214,58.42 C30.1
N$24
  Top 0.254: R14.1 38.1,79.38 38.1,80.64 D6.C | D5.A 48.26,84.45 48.26,85.72 R13.2
  Bottom 0.254: D6.C 39.37,81.28 41.91,83.82 46.99,83.82 D5.A
N$25
  Top 0.254: C31.1 227.97,58.42 226.69,58.42 R2.2 226.06,59.05 223.52,61.59 X1.2 223.52,62.87 223.52,63.5 219.07,67.94 E2.11
N$26  (via drill 0.61)
  Top 0.254: v147.32,46.99 144.78,46.99 144.78,64.77 142.24,67.31 E11.13
  Bottom 0.254: v147.32,46.99 148.59,46.99 159.38,36.2 165.74,36.2 167,37.47 E8.11
N$27
  Top 0.254: E6.12 170.18,8.89 168.91,10.16 168.91,41.91 166.37,44.45 166.37,47.62 163.83,50.16 163.83,54.61 158.75,59.69 158.75,66.04 160.02,67.31 E10.8
N$29  (via drill 0.61)
  Top 0.254: v161.29,64.77 161.29,73.66 162.56,74.93 E10.6
  Bottom 0.254: v161.29,64.77 140.97,64.77 137.79,67.94 E11.11
N$30
  Bottom 0.508: E10.10 165.74,69.22 167,70.48 170.81,70.48 172.09,69.22 E10.13
N$31
  Top 0.254: E9.6 165.1,62.23 165.1,62.87 PAD6.1
N$32
  Top 0.254: E12.3 139.7,92.71 139.7,95.89 C25.2
N$33
  Top 0.254: E9.7 162.56,62.23 162.56,62.87 PAD7.1
N$34
  Top 0.254: E22.1 73.66,77.47 73.66,78.11 PAD18.1
N$35
  Top 0.254: E9.8 160.02,62.23 160.02,62.87 PAD8.1
N$37
  Top 0.254: E9.16 177.8,52.07 177.8,51.44 PAD9.1
N$38
  Top 0.254: E9.15 175.26,52.07 175.26,51.44 PAD42.1
N$39
  Top 0.254: E9.14 172.72,52.07 172.72,51.44 PAD43.1
N$40
  Top 0.254: E9.13 170.18,52.07 170.18,51.44 PAD44.1
N$41
  Top 0.254: E22.2 71.12,77.47 71.12,78.11 PAD19.1
N$42
  Top 0.254: E9.12 167.64,52.07 167.64,51.44 PAD45.1
N$43
  Top 0.254: E22.3 68.58,77.47 68.58,78.11 PAD28.1
N$44
  Top 0.254: E12.4 137.16,92.71 137.16,95.89 C24.1
N$45
  Top 0.254: E12.1 144.78,92.71 144.78,95.89 C25.1
N$46
  Top 0.254: E9.11 165.1,52.07 165.1,51.44 PAD46.1
N$47
  Top 0.254: E9.10 162.56,52.07 162.56,51.44 PAD47.1
N$48
  Top 0.254: E9.9 160.02,52.07 160.02,51.44 PAD48.1
N$49
  Top 0.254: E14.15 116.84,41.91 119.38,39.37 119.38,38.73 T.1
N$50
  Top 0.254: E22.4 66.04,77.47 66.04,78.11 PAD29.1
N$51
  Top 0.254: E22.5 63.5,77.47 63.5,78.11 PAD30.1
N$52
  Top 0.254: E22.6 60.96,77.47 60.96,78.11 PAD31.1
N$53
  Top 0.254: E22.7 58.42,77.47 58.42,78.11 PAD32.1
N$54
  Top 0.254: E22.8 55.88,77.47 55.88,78.11 PAD33.1
N$55
  Top 0.254: E22.16 73.66,67.31 73.66,66.67 PAD34.1
N$56
  Top 0.254: E22.15 71.12,67.31 71.12,66.67 PAD35.1
N$57
  Top 0.254: E22.14 68.58,67.31 68.58,66.67 PAD36.1
N$58
  Top 0.254: E22.13 66.04,67.31 66.04,66.67 PAD37.1
N$59
  Top 0.254: E22.12 63.5,67.31 63.5,66.67 PAD38.1
N$60  (via drill 0.61)
  Top 0.508: v156.84,66.04 157.48,65.41 157.48,11.43 160.02,8.89 E6.8
  Bottom 0.508: E6.8 160.66,6.99 161.93,6.99 E6.9 | v156.84,66.04 167.64,66.04 169.54,67.94 E10.12
N$61
  Top 0.254: E22.11 60.96,67.31 60.96,66.67 PAD39.1
N$68
  Top 0.254: E22.10 58.42,67.31 58.42,66.67 PAD40.1
N$69
  Top 0.254: E22.9 55.88,67.31 55.88,66.67 PAD41.1
N$90
  Top 0.254: E15.15 116.84,69.85 119.38,67.31 119.38,66.67 K.1
N$91
  Top 0.254: E15.14 114.3,69.85 116.84,67.31 116.84,66.67 K.3
N$97
  Top 0.254: E15.13 111.76,69.85 114.3,67.31 114.3,66.67 K.5
N$109
  Top 0.254: E15.12 109.22,69.85 111.76,67.31 111.76,66.67 K.7
N$112
  Top 0.254: E15.11 106.68,69.85 109.22,67.31 109.22,66.67 K.9
N$113
  Top 0.254: E15.10 104.14,69.85 106.68,67.31 106.68,66.67 K.11
N$114
  Top 0.254: E15.7 104.14,77.47 100.33,73.66 100.33,67.94 101.6,66.67 K.15
N$115
  Top 0.254: E15.9 101.6,69.85 104.14,67.31 104.14,66.67 K.13
N$116
  Top 0.254: E14.14 114.3,41.91 116.84,39.37 116.84,38.73 T.3
N$117
  Top 0.254: E14.13 111.76,41.91 114.3,39.37 114.3,38.73 T.5
N$118
  Top 0.254: E14.12 109.22,41.91 111.76,39.37 111.76,38.73 T.7
N$119
  Top 0.254: E14.11 106.68,41.91 109.22,39.37 109.22,38.73 T.9
N$120
  Top 0.254: E14.10 104.14,41.91 106.68,39.37 106.68,38.73 T.11
N$121
  Top 0.254: E14.7 104.14,49.53 100.33,45.72 100.33,40.01 101.6,38.73 T.15
N$122
  Top 0.254: E14.9 101.6,41.91 104.14,39.37 104.14,38.73 T.13
N$123
  Top 0.254: E13.15 116.84,16.51 119.38,13.97 119.38,13.34 P.1
N$124
  Top 0.254: E13.14 114.3,16.51 116.84,13.97 116.84,13.34 P.3
N$125
  Top 0.254: E13.13 111.76,16.51 114.3,13.97 114.3,13.34 P.5
N$126
  Top 0.254: E13.12 109.22,16.51 111.76,13.97 111.76,13.34 P.7
N$127
  Top 0.254: E13.11 106.68,16.51 109.22,13.97 109.22,13.34 P.9
N$128
  Top 0.254: E13.10 104.14,16.51 106.68,13.97 106.68,13.34 P.11
N$129
  Top 0.254: E13.7 104.14,24.13 100.33,20.32 100.33,14.61 101.6,13.34 P.15
N$130
  Top 0.254: E13.9 101.6,16.51 104.14,13.97 104.14,13.34 P.13
P\
  Top 0.254: P.16 102.23,10.16 103.5,10.16 P.14 104.78,10.16 106.05,10.16 P.12 107.31,10.16 108.58,10.16 P.10 109.86,10.16 111.12,10.16 P.8 112.39,10.16 113.67,10.16 P.6 114.94,10.16 116.2,10.16 P.4 117.47,10.16 118.75,10.16 P.2 120.02,10.16 120.02,5.08 162.56,5.08 163.83,6.35 163.83,12.7 165.1,13.97 E6.5
PT
  Top 0.254: 166.37,17.78 167.64,16.51 E6.4 | 166.37,17.78 162.56,21.59 E7.9 162.56,24.13 161.29,25.4 161.29,35.56 162.56,36.83 E8.9 | 166.37,17.78 166.37,27.94 167.64,29.21 E7.4
RBR1  (via drill 0.61)
  Top 0.254: v100.33,87.63 92.71,80.01 92.71,74.93 90.17,72.39 90.17,48.26 91.44,46.99 E19.1 | v170.81,95.89 173.35,98.42 E5.12
  Bottom 0.254: v100.33,87.63 162.56,87.63 v170.81,95.89
RBR2  (via drill 0.61)
  Top 0.254: v80.64,93.98 80.64,59.05 86.36,53.34 E20.6
  Bottom 0.254: v80.64,93.98 81.28,94.61 146.69,94.61 153.03,100.97 174.62,100.97 175.9,99.69 E5.11
RBR3  (via drill 0.61)
  Top 0.254: v149.86,90.17 v149.86,60.33
  Bottom 0.254: v149.86,60.33 92.08,60.33 E20.1 | v149.86,90.17 156.84,97.16 177.16,97.16 178.44,98.42 E5.10
RBR4  (via drill 0.61)
  Top 0.254: v176.53,5.71 181.61,10.79 181.61,81.28 180.34,82.55 180.34,96.52 181.61,97.79 E5.9
  Bottom 0.254: v176.53,5.71 130.81,5.71 127.64,8.89 100.97,8.89 99.69,10.16 88.9,10.16 87,8.26 E17.6
RBR5  (via drill 0.61)
  Top 0.254: v139.7,33.66 140.97,34.92 v140.97,85.72
  Bottom 0.254: v139.7,33.66 139.06,34.29 121.92,34.29 115.57,27.94 91.44,27.94 87,23.5 E18.6 | v140.97,85.72 142.24,87 166.37,87 175.9,96.52 181.61,96.52 183.51,98.42 E5.8
RBR6  (via drill 0.61)
  Top 0.254: v122.56,41.27 130.81,49.53 130.81,80.01 133.35,82.55 133.35,85.09 138.43,90.17 138.43,97.16 143.51,102.23 186.69,102.23 186.69,100.33 E5.7
  Bottom 0.254: v122.56,41.27 102.23,41.27 92.08,31.11 E18.1
RBR7  (via drill 0.61)
  Top 0.254: v182.88,19.05 186.69,22.86 186.69,62.23 189.87,65.41 189.87,66.67 189.23,67.31 189.23,81.28 187.96,82.55 187.96,96.52 189.23,97.79 E5.6
  Bottom 0.254: v182.88,19.05 159.38,19.05 146.69,6.35 131.44,6.35 126.36,11.43 100.97,11.43 97.16,15.24 92.08,15.24 E17.1
RBR8
  Top 0.254: E19.6 86.36,39.37 87.63,40.64 87.63,72.39 90.17,74.93 90.17,79.38 100.97,90.17 110.49,90.17 110.49,92.71 107.95,95.25 107.95,100.33 110.49,102.87 110.49,105.41 113.67,108.58 191.77,108.58 191.77,100.33 E5.5
RRUN
  Top 0.254: E12.10 129.54,82.55 128.27,81.28 128.27,71.12 129.54,69.85 E11.8
  Bottom 0.254: R7.1 41.27,55.88 50.16,64.77 125.73,64.77 128.91,67.94 E11.8
RRUN+
  Top 0.254: R10.2 25.4,48.9 25.4,50.16 D4.C | X3.6 42.55,98.42 29.21,85.09 29.21,81.92 26.67,79.38 26.67,72.39 27.3,71.75 27.3,64.77 20.32,57.78 20.32,54.61 D3.C
  Bottom 0.254: D3.C 20.95,52.7 22.86,50.8 24.13,50.8 D4.C
RRUN-
  Top 0.254: R9.2 15.24,64.14 26.04,74.93 26.04,91.44 33.02,98.42 X3.4
RTS
  Top 0.254: E12.8 127.64,90.81 128.91,90.81 E12.7
  Bottom 0.254: J1.8 73.03,90.17 75.56,92.71 127,92.71 E12.8
RX  (via drill 0.61)
  Top 0.254: v160.02,12.06 158.12,13.97 158.12,71.75 160.02,73.66 | 160.02,73.66 161.29,74.93 161.29,77.47 161.93,78.11 165.1,78.11 165.1,77.47 E10.5 | 160.02,73.66 154.94,78.74 154.94,96.52 153.67,97.79 E5.20
  Bottom 0.254: v160.02,12.06 168.28,12.06 172.09,8.26 E6.13
RX+
  Top 0.254: X3.7 48.26,98.42 48.26,89.53 R11.1
  Bottom 0.254: R13.1 38.73,86.36 41.27,88.9 47.62,88.9 R11.1
RX-
  Top 0.254: R12.2 15.24,84.45 27.94,97.16 27.94,98.42 X3.3
RXD
  Bottom 0.254: E12.13 136.53,84.45 135.25,85.72 73.66,85.72 71.75,87.63 J1.3
RXE  (via drill 0.61)
  Top 0.254: v152.4,71.75 152.4,100.33 146.69,100.33 143.51,97.16 143.51,89.53 140.34,89.53 135.25,84.45 E12.12
  Bottom 0.254: v152.4,71.75 153.67,70.48 160.66,70.48 161.93,69.22 E10.9
RXL\
  Top 0.254: R14.2 48.9,78.74 57.15,70.48 57.15,61.59 67.31,51.44 67.31,6.99 68.58,5.71 98.42,5.71 98.42,6.35 100.97,8.89 119.38,8.89 119.38,4.45 167,4.45 167,6.99 E6.11
STOPB
  Top 0.254: E5.36 191.77,85.09 193.04,86.36 193.04,105.41 STOPB.2
T\
  Top 0.254: T.16 102.23,35.56 103.5,35.56 T.14 104.78,35.56 106.05,35.56 T.12 107.31,35.56 108.58,35.56 T.10 109.86,35.56 111.12,35.56 T.8 | T.6 114.94,35.56 116.2,35.56 T.4 117.47,35.56 118.75,35.56 T.2 119.38,34.92 120.65,33.66 120.65,5.71 160.66,5.71 161.29,6.35 161.29,12.7 162.56,13.97 E6.6
  Bottom 0.254: T.6 113.67,35.56 112.39,35.56 T.8
TBR1  (via drill 0.61)
  Top 0.254: v168.28,87.63 166.37,85.72 166.37,85.09 E5.26
  Bottom 0.254: v168.28,87.63 172.72,87.63 173.35,87 238.12,87 238.12,46.99 234.95,43.81 230.5,43.81 229.24,45.09 E1.18
TBR2  (via drill 0.61)
  Top 0.254: v214.63,71.75 214.63,57.78 217.17,55.24 217.17,52.07 222.88,46.35 E1.16
  Bottom 0.254: v214.63,71.75 212.72,73.66 175.26,73.66 173.99,74.93 173.99,81.92 170.81,81.92 169.54,83.19 E5.27
TBR3
  Bottom 0.254: E5.28 172.09,84.45 173.35,85.72 177.16,85.72 177.8,85.09 177.8,81.28 210.19,81.28 213.36,78.11 214,78.11 214.63,77.47 214.63,73.03 232.41,73.03 237.49,67.94 237.49,48.26 220.98,48.26 219.07,46.35 E1.14
TBR4  (via drill 0.61)
  Top 0.254: v198.75,78.74 209.55,67.94 209.55,50.8 213.36,46.99 E1.12
  Bottom 0.254: v198.75,78.74 179.07,78.74 174.62,83.19 E5.29
TBR5  (via drill 0.61)
  Top 0.254: v180.34,48.9 180.34,78.74 176.53,82.55 E5.30
  Bottom 0.254: v180.34,48.9 186.06,54.61 209.55,54.61 210.19,55.24 211.46,55.24 212.72,53.98 E1.9
TBR6  (via drill 0.61)
  Top 0.254: v215.26,78.74 217.17,78.74 217.17,56.52 218.44,55.24 218.44,54.61 E1.7
  Bottom 0.254: v215.26,78.74 214,78.74 210.82,81.92 180.97,81.92 179.71,83.19 E5.31
TBR7  (via drill 0.61)
  Top 0.254: v187.32,64.14 187.32,76.83 181.61,82.55 E5.32
  Bottom 0.254: v187.32,64.14 194.31,57.15 211.46,57.15 213.36,55.24 221.62,55.24 222.88,53.98 E1.5
TBR8  (via drill 0.61)
  Top 0.254: v188.59,65.41 188.59,78.11 184.15,82.55 E5.33
  Bottom 0.254: v188.59,65.41 196.22,57.78 212.09,57.78 214,55.88 226.06,55.88 227.97,53.98 E1.3
TCF\  (via drill 0.61)
  Top 0.254: v148.59,45.72 148.59,71.12 144.78,74.93 E11.1
  Bottom 0.254: v148.59,45.72 162.56,31.75 E7.6
TPC\  (via drill 0.61)
  Top 0.254: v156.21,27.94 155.57,28.57 v155.57,76.2 | v158.12,76.83 158.75,77.47 158.75,82.55 E5.23
  Bottom 0.254: v156.21,27.94 160.02,24.13 E7.8 | v155.57,76.2 156.21,76.83 v158.12,76.83
TPF  (via drill 0.61)
  Top 0.254: v190.5,59.69 190.5,64.77 193.04,67.31 E4.6 | v137.16,58.42 133.35,62.23 133.35,73.66 134.62,74.93 E11.5
  Bottom 0.254: v190.5,59.69 189.23,58.42 v137.16,58.42
TRE  (via drill 0.61)
  Top 0.254: v139.7,79.38 139.7,77.47 E11.3
  Bottom 0.254: v139.7,79.38 141.6,81.28 163.83,81.28 165.1,82.55 165.1,85.72 163.19,85.72 161.93,84.45 E5.24
TSF  (via drill 0.61)
  Top 0.254: v191.77,41.91 195.58,45.72 195.58,67.31 E4.7
  Bottom 0.254: v191.77,41.91 163.83,41.91 160.66,38.73 E8.8
TX
  Bottom 0.254: 130.18,81.92 102.23,81.92 100.33,80.01 45.09,80.01 41.27,76.2 R5.1 | 130.18,81.92 131.44,83.19 E12.11 | 130.18,81.92 161.93,81.92 163.19,83.19 E5.25
TX+
  Top 0.254: R6.2 25.4,69.22 25.4,70.48 D2.C | X3.5 37.47,101.6 34.92,104.14 29.84,104.14 29.84,96.52 21.59,88.27 21.59,76.2 20.32,74.93 D1.C
  Bottom 0.254: D1.C 20.95,73.03 22.86,71.12 24.13,71.12 D2.C
TX-
  Top 0.254: R4.2 12.7,84.45 22.86,94.61 22.86,98.42 X3.2
TXD
  Bottom 0.254: E12.14 139.06,84.45 137.16,86.36 90.81,86.36 85.09,92.08 79.38,92.08 76.2,88.9 69.22,88.9 68.58,88.27 J1.2
VCC
  Top 0.508: C5.1 233.68,70.48 232.41,71.75 232.41,79.38 233.68,80.64 233.68,89.53 C6.1 | C22.1 230.5,25.4 224.16,31.75 C23.+ 224.16,34.29 224.16,34.92 233.68,44.45 E1.20 | E2.16 231.14,67.31 234.95,63.5 234.95,48.9 236.22,47.62 C4.1 | 176.53,24.13 177.8,25.4 177.8,26.04 C2.1 | 176.53,24.13 175.9,23.5 E7.14 | 176.53,24.13 176.53,10.79 177.8,9.53 C1.1 | 176.53,24.13 176.53,35.56 175.26,36.83 E8.14 | 5/8.3 205.74,105.41 205.74,104.14 201.93,100.33 E5.1 201.93,97.79 203.2,96.52 203.2,87.63 | 203.2,87.63 203.84,88.27 203.84,88.9 C8.1 | 203.2,87.63 200.03,84.45 E5.39 199.39,82.55 196.85,80.01 196.85,71.12 198.12,69.85 E4.8 | C3.1 177.8,40.01 179.07,41.27 179.07,50.16 179.71,50.8 179.71,64.14 175.9,67.94 E10.14 | C27.2 147.32,98.42 148.59,97.16 148.59,87 147.32,85.72 C14.1 | E11.10 134.62,69.85 137.16,72.39 137.16,74.93 E11.4 | E11.14 144.78,69.85 144.78,72.39 142.24,74.93 E11.2 142.24,77.47 142.24,80.01 144.78,82.55 E12.16 | Q1.1 27.94,78.11 29.21,76.83 29.21,60.33 27.94,59.05 Q2.1 27.94,57.78 27.94,27.3 31.75,23.5 IC2.3 | R11.2 38.1,88.27 36.83,87 36.83,83.82 D5.C | E15.6 106.05,79.38 104.78,80.64 95.25,80.64 95.25,71.75 93.98,70.48 C20.1 | 92.71,20.32 92.71,10.79 93.98,9.53 C16.1 | 92.71,20.32 91.44,21.59 E18.8 | 92.71,20.32 92.71,35.56 91.44,36.83 E19.8 | E13.16 118.75,18.41 113.67,23.5 106.68,23.5 106.68,24.13 E13.6 | E21.8 91.44,67.31 92.71,66.04 92.71,57.78 91.44,56.52 91.44,53.34 E20.8
  Bottom 0.508: C5.1 233.04,69.85 232.41,69.85 231.78,69.22 E2.16 230.5,69.22 229.24,70.48 200.66,70.48 | E3.16 231.78,89.53 232.41,90.17 233.04,90.17 C6.1 | E1.20 234.31,46.35 234.95,46.99 235.59,46.99 C4.1 | E8.14 175.9,38.73 176.53,39.37 177.16,39.37 C3.1 | E6.14 175.9,8.26 176.53,8.89 177.16,8.89 C1.1 | E4.8 198.75,69.22 199.39,69.85 200.03,69.85 C7.1 | 200.66,70.48 179.07,70.48 178.44,69.85 C15.1 177.16,69.85 176.53,69.85 175.9,69.22 E10.14 174.62,69.22 170.81,73.03 151.13,73.03 147.96,69.85 C13.1 147.32,70.48 144.78,70.48 | 200.66,70.48 C7.1 | STOPB.3 195.58,105.41 201.29,99.69 E5.1 | E5.34 187.32,83.19 188.59,83.19 E5.35 189.87,84.45 191.13,85.72 197.49,85.72 198.75,84.45 E5.39 | 200.66,70.48 C7.1 | E16.16 120.02,97.16 120.65,97.79 121.28,97.79 C12.1 | E16.6 106.05,104.78 104.78,106.05 100.97,106.05 100.33,105.41 100.33,98.42 121.92,98.42 C12.1 | E12.16 145.41,84.45 146.05,85.09 146.69,85.09 C14.1 | 141.6,70.48 140.34,69.22 E11.12 | 144.78,70.48 141.6,70.48 | 144.78,70.48 144.78,69.85 E11.14 | 141.6,70.48 134.62,70.48 | 134.62,70.48 124.46,70.48 122.56,72.39 C11.1 121.28,72.39 120.65,72.39 120.02,71.75 E15.16 118.75,70.48 117.47,69.22 93.98,69.22 C20.1 | 134.62,70.48 134.62,69.85 E11.10 | C12.1 122.56,97.79 145.41,97.79 146.69,99.06 C27.2 | 33.66,80.64 31.75,78.74 28.57,78.74 Q1.1 | 33.66,80.64 36.83,83.82 D5.C | E21.8 92.08,69.22 92.71,69.85 93.34,69.85 C20.1 | C20.1 93.98,70.48 77.47,70.48 76.83,69.85 C21.1 76.2,70.48 43.81,70.48 33.66,80.64 | C10.1 121.28,44.45 120.65,44.45 120.02,43.81 E14.16 118.75,43.81 113.67,48.9 108.58,48.9 107.31,50.16 E14.6 | E20.8 92.08,52.7 92.71,53.34 93.34,53.34 C19.1 94.61,53.34 104.14,53.34 106.05,51.44 E14.6
  Bottom 0.508: E13.16 120.02,18.41 120.65,19.05 121.28,19.05 C9.1 | E19.8 92.08,38.73 92.71,39.37 93.34,39.37 C18.1 94.61,39.37 95.25,39.37 106.05,50.16 E14.6 | E17.8 92.08,8.26 92.71,8.89 93.34,8.89 C16.1 | E18.8 92.08,23.5 92.71,24.13 93.34,24.13 C17.1 93.98,23.5 104.78,23.5 106.05,24.77 E13.6

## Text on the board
Bottom: Posibus Serial Interface | VRS
tPlace: Posibus Serial Interface | VRS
